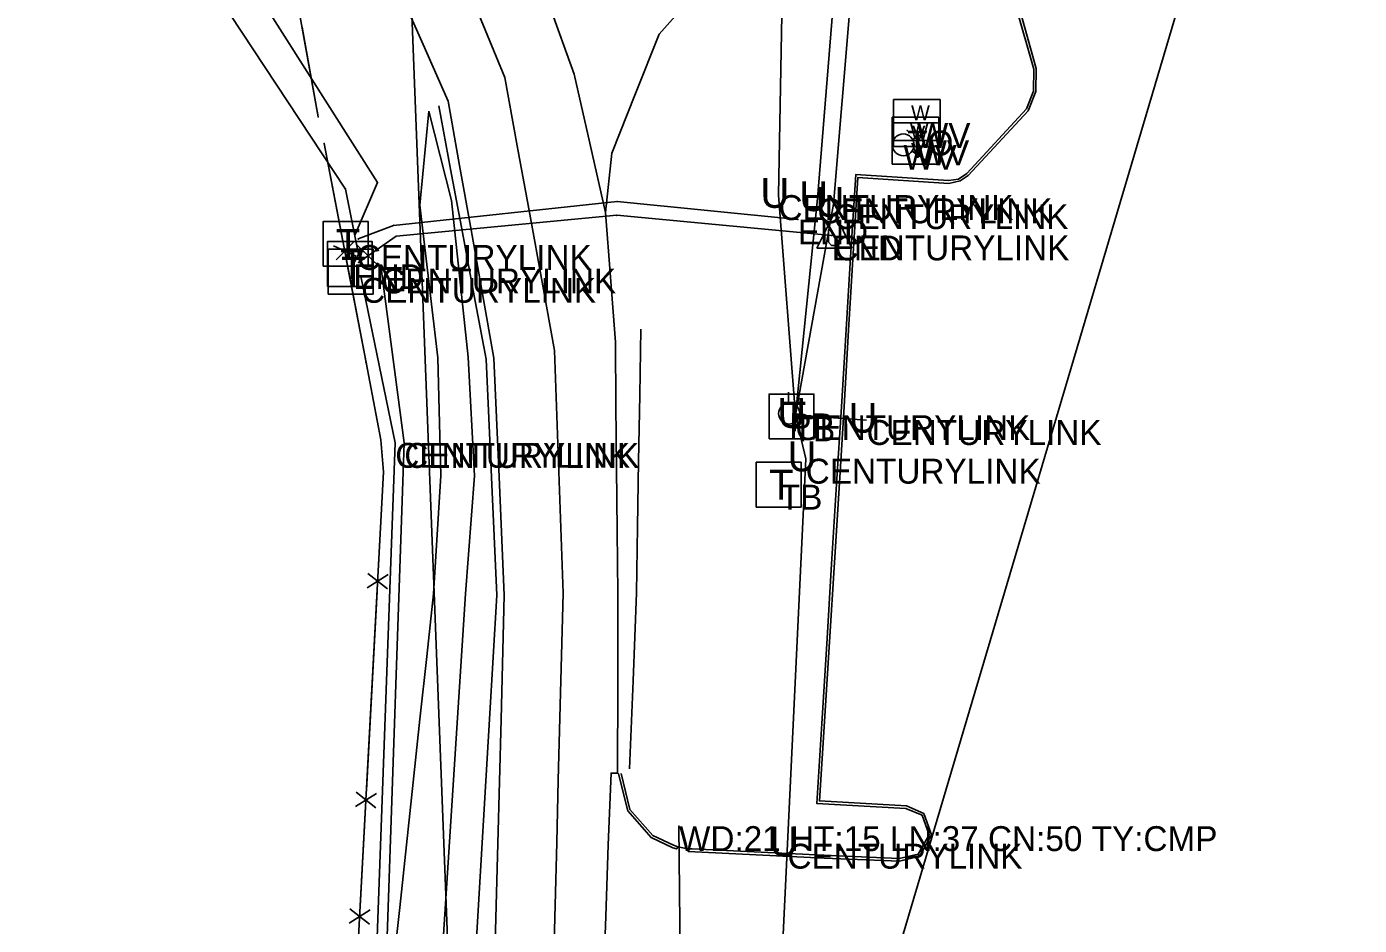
# Model space of a CAD drawing. Extents: x 675481 to 678499, y 212715 to 215285.
# Drawn here: x 677784.7 to 678052.3, y 214307.3 to 214487.7 of the extents above; entities that cross this region are included whole.
import ezdxf

# ---------------------------------------------------------------- set-up
doc = ezdxf.new("R2010")
doc.units = 0
for name, color, linetype in [('Default', 7, 'Continuous'), ('S_BASELINE', 7, 'Continuous'), ('S_CURB', 7, 'Continuous'), ('S_DITCHLINE', 7, 'Continuous'), ('S_DRG_PT_SYM', 7, 'Continuous'), ('S_EDGE_CONCRETE', 7, 'Continuous'), ('S_EDGE_PAVEMENT', 7, 'Continuous'), ('S_FENCE', 7, 'Continuous'), ('S_FIBER_OPTIC_CABLE', 7, 'Continuous'), ('S_FIBER_OPTIC_CABLE_ANNOT', 7, 'Continuous'), ('S_GAS_UTILITIES', 7, 'Continuous'), ('S_GRD_PT_SYM', 7, 'Continuous'), ('S_MISC_TOPO_POINT', 7, 'Continuous'), ('S_MSC_PT_SYM', 7, 'Continuous'), ('S_PAVEMENT_CROWN', 7, 'Continuous'), ('S_SHOULDER', 7, 'Continuous'), ('S_SIDE_DRAIN', 7, 'Continuous'), ('S_SIDE_DRAIN_ANNOT', 7, 'Continuous'), ('S_TELEPHONE_UTILITIES', 7, 'Continuous'), ('S_TELEPHONE_UTILITIES_ANNOT', 7, 'Continuous'), ('S_UNDERGROUND_CABLE', 7, 'Continuous'), ('S_UNDERGROUND_CABLE_ANNOT', 7, 'Continuous'), ('S_UTILITY_POLE', 7, 'Continuous'), ('S_UTILITY_POLE_ANNOT', 7, 'Continuous'), ('S_UTL_PT_SYM', 7, 'Continuous'), ('S_WATER_UTILITIES', 7, 'Continuous'), ('S_WATER_UTILITIES_ANNOT', 7, 'Continuous')]:
    doc.layers.add(name, color=color, linetype=linetype)

msp = doc.modelspace()

# ---------------------------------------------------------------- linework, layer by layer
at = {"layer": 'S_BASELINE'}
msp.add_line((677859.18, 214564.08), (677899.68, 213513.2), dxfattribs=at)
at = {"layer": 'S_CURB'}
for points in [[(677983.38, 214491.58), (677986.88, 214479.15), (677986.83, 214474.8), (677985.44, 214471.22), (677973.47, 214458.27), (677971.75, 214457.13), (677969.79, 214456.81), (677951.14, 214458.03), (677950.18, 214442.49), (677949.21, 214426.95), (677948.25, 214411.4), (677947.29, 214395.86), (677946.3, 214379.85), (677945.31, 214363.84), (677944.31, 214347.82), (677943.32, 214331.81), (677961.2, 214330.78), (677964.45, 214329.43), (677965.91, 214325.49), (677963.71, 214321.61), (677959.85, 214320.78), (677943.18, 214321.46), (677918.32, 214322.67), (677917.5, 214322.66)], [(677915.42, 214323.11), (677914.54, 214323.4), (677910.41, 214325.37), (677905.8, 214330.6), (677904.04, 214337.81)]]:
    msp.add_lwpolyline(points, dxfattribs=at)
at = {"layer": 'S_DITCHLINE'}
for points in [[(677865.39, 214470.74), (677863.64, 214451.91), (677865.44, 214436.57), (677867.24, 214421.23), (677867.8, 214397.65), (677866.34, 214373.89), (677864.99, 214361.29), (677863.63, 214348.69), (677862.28, 214336.09), (677860.92, 214323.49), (677859.57, 214310.89), (677858.21, 214298.29)], [(677865.39, 214470.73), (677869.96, 214452.85), (677871.64, 214437.1), (677873.32, 214421.35), (677874.57, 214397.53), (677872.78, 214373.88), (677871.17, 214348.99), (677869.56, 214324.09), (677867.96, 214299.2)]]:
    msp.add_lwpolyline(points, dxfattribs=at)
at = {"layer": 'S_DRG_PT_SYM'}
msp.add_lwpolyline([(677915.65, 214327.24), (677915.65, 214327.29), (677915.65, 214327.24), (677915.6, 214327.24), (677915.65, 214327.24), (677915.65, 214327.19), (677915.65, 214327.24), (677915.7, 214327.24)], dxfattribs=at)
at = {"layer": 'S_EDGE_CONCRETE'}
for points in [[(677983.94, 214491.55), (677987.36, 214479.34), (677987.34, 214474.7), (677985.8, 214470.8), (677973.74, 214457.87), (677972.1, 214456.76), (677969.82, 214456.26), (677951.58, 214457.47), (677950.65, 214442.13), (677949.72, 214426.8), (677948.79, 214411.47), (677947.86, 214396.13), (677946.86, 214380.17), (677945.86, 214364.22), (677944.85, 214348.26), (677943.85, 214332.3), (677961.35, 214331.29), (677964.81, 214329.76), (677966.35, 214325.51), (677964.01, 214321.19), (677959.9, 214320.23), (677944.79, 214320.79), (677931.14, 214321.48), (677917.49, 214322.16), (677917.37, 214322.7), (677915.49, 214323.09), (677915.18, 214322.67), (677914.38, 214322.92), (677910.03, 214324.97), (677905.39, 214330.3), (677903.51, 214337.76)], [(677903.51, 214337.76), (677903.32, 214337.87)]]:
    msp.add_lwpolyline(points, dxfattribs=at)
at = {"layer": 'S_EDGE_PAVEMENT'}
for points in [[(677836.94, 214575.26), (677848.31, 214564.09), (677859.68, 214552.92), (677870.73, 214537.2), (677877.66, 214521.64), (677884.59, 214506.09), (677889.61, 214492.12), (677894.63, 214478.16), (677897.75, 214464.3), (677900.87, 214450.43), (677901.87, 214437.41), (677902.87, 214424.38), (677903, 214411.76), (677903.13, 214399.15), (677903.26, 214386.53), (677903.39, 214373.91), (677903.35, 214355.89), (677903.32, 214337.87), (677902, 214337.89), (677901.46, 214323.49), (677900.93, 214309.09), (677900.4, 214294.69)], [(677820.84, 214556.56), (677834.52, 214538.62), (677848.19, 214520.68), (677853.46, 214508.7), (677858.73, 214496.72), (677864, 214484.74), (677869.27, 214472.76), (677871.58, 214459.86), (677873.89, 214446.96), (677876.2, 214434.06), (677878.5, 214421.16), (677879.53, 214397.37), (677880.55, 214373.58), (677879.91, 214348.66), (677879.26, 214323.75), (677878.61, 214298.83)], [(677902.14, 214462.33), (677906.9, 214474.28), (677911.66, 214486.23), (677926.85, 214503.34), (677936.11, 214511.45), (677948.81, 214516.49), (677961.5, 214521.54), (677974.19, 214526.58), (677986.88, 214531.62), (677998.97, 214534.94), (678011.07, 214538.25), (678023.16, 214541.57), (678035.25, 214544.88), (678054.98, 214548.6)], [(677900.87, 214450.43), (677902.14, 214462.33)]]:
    msp.add_lwpolyline(points, dxfattribs=at)
at = {"layer": 'S_FENCE'}
for p, q in [((677835.73, 214511.24), (677843.18, 214469.62)), ((677844.39, 214464.27), (677852.81, 214420.33)), ((677846.25, 214443.71), (677850.81, 214441.66)), ((677850.27, 214444.48), (677846.79, 214440.89)), ((677852.81, 214420.33), (677855.78, 214404.81)), ((677855.78, 214404.81), (677856.31, 214398.38)), ((677856.31, 214398.38), (677827.7, 213863.61)), ((677857.26, 214377.74), (677853.01, 214375.09)), ((677853.17, 214377.96), (677857.1, 214374.87)), ((677850.82, 214334.04), (677854.75, 214330.95)), ((677854.91, 214333.82), (677850.66, 214331.17)), ((677853.66, 214310.43), (677849.41, 214307.78)), ((677849.57, 214310.65), (677853.5, 214307.56))]:
    msp.add_line(p, q, dxfattribs=at)
for points in [[(677839.96, 214487.61), (677843.18, 214469.62)], [(677839.96, 214487.61), (677843.18, 214469.62)], [(677839.96, 214487.61), (677843.18, 214469.62)], [(677844.39, 214464.27), (677848.15, 214444.65)], [(677848.9, 214440.72), (677852.81, 214420.33)], [(677852.81, 214420.33), (677855.78, 214404.81)], [(677855.78, 214404.81), (677856.31, 214398.38)], [(677856.31, 214398.38), (677855.24, 214378.41)], [(677855.03, 214374.42), (677852.89, 214334.49)], [(677852.71, 214331.06), (677851.64, 214311.1)]]:
    msp.add_lwpolyline(points, dxfattribs=at)
at = {"layer": 'S_FIBER_OPTIC_CABLE'}
for p, q in [((677770.28, 214573.85), (677848.71, 214455.13)), ((677780.88, 214573.35), (677855.11, 214456.45)), ((677848.71, 214455.13), (677851.28, 214442.06)), ((677855.11, 214456.45), (677850.59, 214446.01)), ((677858.32, 214447.83), (677903.22, 214452.63)), ((677903.22, 214452.63), (677939.51, 214449)), ((677858.85, 214445.65), (677903.14, 214449.86)), ((677903.14, 214449.86), (677946.31, 214445.79)), ((677851.25, 214445.1), (677858.32, 214447.83)), ((677850.59, 214446.01), (677850.58, 214446.02)), ((677850.95, 214443.89), (677855.86, 214439.17)), ((677851.32, 214440.41), (677858.85, 214445.65)), ((677851.28, 214442.06), (677850.26, 214440.04)), ((677855.86, 214439.17), (677860.49, 214404.15)), ((677851.83, 214437.29), (677858.68, 214404.17)), ((677858.68, 214404.17), (677853.43, 214262.21)), ((677860.49, 214404.15), (677855.5, 214261.83))]:
    msp.add_line(p, q, dxfattribs=at)
at = {"layer": 'S_GAS_UTILITIES'}
msp.add_line((677939.09, 214232.8), (678023.84, 214518.55), dxfattribs=at)
at = {"layer": 'S_GRD_PT_SYM'}
for points in [[(677961.47, 214466.85), (677961.47, 214466.9), (677961.47, 214466.85), (677961.42, 214466.85), (677961.47, 214466.85), (677961.47, 214466.8), (677961.47, 214466.85), (677961.52, 214466.85)], [(677902.14, 214337.88), (677902.14, 214337.93), (677902.14, 214337.88), (677902.09, 214337.88), (677902.14, 214337.88), (677902.14, 214337.83), (677902.14, 214337.88), (677902.19, 214337.88)]]:
    msp.add_lwpolyline(points, dxfattribs=at)
at = {"layer": 'S_MSC_PT_SYM'}
for points in [[(677843.18, 214469.62), (677843.18, 214469.67), (677843.18, 214469.62), (677843.13, 214469.62), (677843.18, 214469.62), (677843.18, 214469.57), (677843.18, 214469.62), (677843.23, 214469.62)], [(677844.39, 214464.27), (677844.39, 214464.32), (677844.39, 214464.27), (677844.34, 214464.27), (677844.39, 214464.27), (677844.39, 214464.22), (677844.39, 214464.27), (677844.44, 214464.27)], [(677852.81, 214420.33), (677852.81, 214420.38), (677852.81, 214420.33), (677852.76, 214420.33), (677852.81, 214420.33), (677852.81, 214420.28), (677852.81, 214420.33), (677852.86, 214420.33)], [(677855.78, 214404.81), (677855.78, 214404.86), (677855.78, 214404.81), (677855.73, 214404.81), (677855.78, 214404.81), (677855.78, 214404.76), (677855.78, 214404.81), (677855.83, 214404.81)], [(677856.31, 214398.38), (677856.31, 214398.43), (677856.31, 214398.38), (677856.26, 214398.38), (677856.31, 214398.38), (677856.31, 214398.33), (677856.31, 214398.38), (677856.36, 214398.38)]]:
    msp.add_lwpolyline(points, dxfattribs=at)
at = {"layer": 'S_PAVEMENT_CROWN'}
msp.add_lwpolyline([(677830.11, 214566.89), (677845, 214547.51), (677859.89, 214528.12), (677865.08, 214515.47), (677870.27, 214502.82), (677875.46, 214490.17), (677880.66, 214477.51), (677883.16, 214463.81), (677885.67, 214450.11), (677888.18, 214436.41), (677890.68, 214422.71), (677891.52, 214398.36), (677892.37, 214374.01), (677892.05, 214361.49), (677891.73, 214348.97), (677891.41, 214336.45), (677891.1, 214323.93), (677890.78, 214311.4), (677890.46, 214298.88)], dxfattribs=at)
at = {"layer": 'S_SHOULDER'}
for points in [[(677867.4, 214471.84), (677869.79, 214459.13), (677872.17, 214446.42), (677874.55, 214433.71), (677876.94, 214421), (677878.02, 214397.3), (677879.09, 214373.6), (677877.62, 214348.74), (677876.14, 214323.88), (677874.67, 214299.02)], [(677907.97, 214426.99), (677907.76, 214413.76), (677907.55, 214400.52), (677907.34, 214387.29), (677907.13, 214374.06), (677906.43, 214356.41), (677905.73, 214338.76)]]:
    msp.add_lwpolyline(points, dxfattribs=at)
at = {"layer": 'S_SIDE_DRAIN'}
msp.add_line((677915.65, 214327.24), (677915.98, 214290.76), dxfattribs=at)
at = {"layer": 'S_TELEPHONE_UTILITIES'}
for points in [[(677844.2, 214439.62), (677844.2, 214448.62), (677853.2, 214448.62), (677853.2, 214439.62)], [(677845.06, 214435.56), (677845.06, 214444.56), (677854.06, 214444.56), (677854.06, 214435.56)], [(677845.23, 214434.04), (677845.23, 214443.04), (677854.23, 214443.04), (677854.23, 214434.04)], [(677933.75, 214404.96), (677933.75, 214413.96), (677942.75, 214413.96), (677942.75, 214404.96)], [(677931.17, 214391.27), (677931.17, 214400.27), (677940.17, 214400.27), (677940.17, 214391.27)]]:
    msp.add_lwpolyline(points, close=True, dxfattribs=at)
at = {"layer": 'S_UNDERGROUND_CABLE'}
for p, q in [((677935.63, 214453.9), (677936.41, 214495.85)), ((677943.45, 214453.24), (677946.88, 214495.38)), ((677946.68, 214452.08), (677950.17, 214493.98)), ((677939.03, 214409.72), (677935.63, 214453.9)), ((677939.03, 214409.72), (677943.45, 214453.24)), ((677939.03, 214409.72), (677946.68, 214452.08)), ((677946.87, 214450.33), (677943.34, 214443.24)), ((677946.87, 214450.33), (677950.36, 214443.24)), ((677945.67, 214444.48), (677945.67, 214446.92)), ((677948.03, 214446.92), (677948.03, 214444.48)), ((677946.29, 214443.82), (677945.67, 214444.48)), ((677947.49, 214443.82), (677946.29, 214443.82)), ((677948.03, 214444.48), (677947.49, 214443.82)), ((677943.34, 214443.24), (677950.36, 214443.24)), ((677939.03, 214409.72), (677941.1, 214400.99)), ((677939.03, 214409.72), (677953.32, 214408.75)), ((677941.1, 214400.99), (677937.44, 214323.71)), ((677937.44, 214323.71), (677933.51, 214243.69))]:
    msp.add_line(p, q, dxfattribs=at)
at = {"layer": 'S_UTILITY_POLE'}
msp.add_line((677937.66, 214412.21), (677937.66, 214414.32), dxfattribs=at)
msp.add_circle((677937.78, 214410.07), 2.13, dxfattribs=at)
at = {"layer": 'S_UTL_PT_SYM'}
for points in [[(677848.71, 214455.13), (677848.71, 214455.18), (677848.71, 214455.13), (677848.66, 214455.13), (677848.71, 214455.13), (677848.71, 214455.08), (677848.71, 214455.13), (677848.76, 214455.13)], [(677855.11, 214456.45), (677855.11, 214456.5), (677855.11, 214456.45), (677855.06, 214456.45), (677855.11, 214456.45), (677855.11, 214456.4), (677855.11, 214456.45), (677855.16, 214456.45)], [(677903.22, 214452.63), (677903.22, 214452.68), (677903.22, 214452.63), (677903.17, 214452.63), (677903.22, 214452.63), (677903.22, 214452.58), (677903.22, 214452.63), (677903.27, 214452.63)], [(677903.14, 214449.86), (677903.14, 214449.91), (677903.14, 214449.86), (677903.09, 214449.86), (677903.14, 214449.86), (677903.14, 214449.81), (677903.14, 214449.86), (677903.19, 214449.86)], [(677939.51, 214449), (677939.51, 214449.05), (677939.51, 214449), (677939.46, 214449), (677939.51, 214449), (677939.51, 214448.95), (677939.51, 214449), (677939.56, 214449)], [(677858.32, 214447.83), (677858.32, 214447.88), (677858.32, 214447.83), (677858.27, 214447.83), (677858.32, 214447.83), (677858.32, 214447.79), (677858.32, 214447.83), (677858.37, 214447.83)], [(677850.58, 214446.02), (677850.58, 214446.07), (677850.58, 214446.02), (677850.53, 214446.02), (677850.58, 214446.02), (677850.58, 214445.97), (677850.58, 214446.02), (677850.63, 214446.02)], [(677850.59, 214446.01), (677850.59, 214446.06), (677850.59, 214446.01), (677850.54, 214446.01), (677850.59, 214446.01), (677850.59, 214445.96), (677850.59, 214446.01), (677850.64, 214446.01)], [(677850.95, 214443.89), (677850.95, 214443.94), (677850.95, 214443.89), (677850.9, 214443.89), (677850.95, 214443.89), (677850.95, 214443.84), (677850.95, 214443.89), (677851, 214443.89)], [(677851.25, 214445.1), (677851.25, 214445.15), (677851.25, 214445.1), (677851.2, 214445.1), (677851.25, 214445.1), (677851.25, 214445.05), (677851.25, 214445.1), (677851.3, 214445.1)], [(677858.85, 214445.65), (677858.85, 214445.7), (677858.85, 214445.65), (677858.8, 214445.65), (677858.85, 214445.65), (677858.85, 214445.6), (677858.85, 214445.65), (677858.9, 214445.65)], [(677946.31, 214445.79), (677946.31, 214445.84), (677946.31, 214445.79), (677946.26, 214445.79), (677946.31, 214445.79), (677946.31, 214445.74), (677946.31, 214445.79), (677946.36, 214445.79)], [(677851.28, 214442.06), (677851.28, 214442.11), (677851.28, 214442.06), (677851.22, 214442.06), (677851.28, 214442.06), (677851.28, 214442.01), (677851.28, 214442.06), (677851.33, 214442.06)], [(677850.26, 214440.04), (677850.26, 214440.09), (677850.26, 214440.04), (677850.21, 214440.04), (677850.26, 214440.04), (677850.26, 214439.99), (677850.26, 214440.04), (677850.31, 214440.04)], [(677851.32, 214440.41), (677851.32, 214440.46), (677851.32, 214440.41), (677851.26, 214440.41), (677851.32, 214440.41), (677851.32, 214440.36), (677851.32, 214440.41), (677851.36, 214440.41)], [(677855.86, 214439.17), (677855.86, 214439.21), (677855.86, 214439.17), (677855.81, 214439.17), (677855.86, 214439.17), (677855.86, 214439.12), (677855.86, 214439.17), (677855.91, 214439.17)], [(677851.83, 214437.29), (677851.83, 214437.34), (677851.83, 214437.29), (677851.78, 214437.29), (677851.83, 214437.29), (677851.83, 214437.24), (677851.83, 214437.29), (677851.88, 214437.29)], [(677858.68, 214404.17), (677858.68, 214404.22), (677858.68, 214404.17), (677858.62, 214404.17), (677858.68, 214404.17), (677858.68, 214404.12), (677858.68, 214404.17), (677858.73, 214404.17)], [(677860.49, 214404.15), (677860.49, 214404.19), (677860.49, 214404.15), (677860.45, 214404.15), (677860.49, 214404.15), (677860.49, 214404.1), (677860.49, 214404.15), (677860.55, 214404.15)]]:
    msp.add_lwpolyline(points, dxfattribs=at)
at = {"layer": 'S_WATER_UTILITIES'}
for p, q in [((677958.7, 214473.07), (677968.11, 214473.07)), ((677958.7, 214463.66), (677958.7, 214473.07)), ((677968.11, 214473.07), (677968.11, 214463.66)), ((677958.44, 214469.56), (677967.86, 214469.56)), ((677958.44, 214460.14), (677958.44, 214469.56)), ((677958.7, 214468.38), (677968.11, 214468.38)), ((677967.86, 214469.56), (677967.86, 214460.14)), ((677962.59, 214465.04), (677965.41, 214466.77)), ((677958.44, 214464.87), (677967.86, 214464.87)), ((677968.11, 214463.66), (677958.7, 214463.66)), ((677962.47, 214462.73), (677965.37, 214460.81)), ((677967.86, 214460.14), (677958.44, 214460.14))]:
    msp.add_line(p, q, dxfattribs=at)
msp.add_circle((677960.69, 214463.99), 2.18, dxfattribs=at)

# ---------------------------------------------------------------- texts
at = {"layer": 'Default'}
for p in [(677932, 214451.35), (677939.82, 214450.69), (677943.05, 214449.53), (677935.4, 214407.18), (677935.4, 214407.18), (677935.4, 214407.18), (677935.4, 214407.18), (677935.4, 214407.18), (677949.69, 214406.21), (677937.47, 214398.45), (677933.81, 214321.16)]:
    msp.add_text('U', height=6, rotation=360, dxfattribs=at).set_placement(p)
at = {"layer": 'S_FIBER_OPTIC_CABLE_ANNOT'}
for s, p in [('END', (677939.51, 214444)), ('CENTURYLINK', (677850.95, 214438.89)), ('END', (677946.31, 214440.79)), ('END', (677850.26, 214435.04)), ('CENTURYLINK', (677855.86, 214434.17)), ('CENTURYLINK', (677851.83, 214432.29)), ('CENTURYLINK', (677858.68, 214399.17)), ('CENTURYLINK', (677860.49, 214399.15))]:
    msp.add_text(s, height=5, dxfattribs=at).set_placement(p)
at = {"layer": 'S_MISC_TOPO_POINT'}
msp.add_text('TO', height=5, dxfattribs=at).set_placement((677961.47, 214461.85))
at = {"layer": 'S_SIDE_DRAIN_ANNOT'}
msp.add_text('WD:21 HT:15 LN:37 CN:50 TY:CMP', height=5, dxfattribs=at).set_placement((677915.65, 214322.24))
at = {"layer": 'S_TELEPHONE_UTILITIES'}
for p in [(677846.76, 214441.12), (677847.62, 214437.06), (677847.79, 214435.54), (677936.31, 214406.46), (677933.74, 214392.77)]:
    msp.add_text('T', height=6, rotation=360, dxfattribs=at).set_placement(p)
at = {"layer": 'S_TELEPHONE_UTILITIES_ANNOT'}
for p in [(677938.48, 214404.48), (677935.9, 214390.78)]:
    msp.add_text('TB', height=5, dxfattribs=at).set_placement(p)
at = {"layer": 'S_UNDERGROUND_CABLE_ANNOT'}
for p in [(677935.63, 214448.9), (677943.45, 214448.24), (677946.68, 214447.08), (677939.03, 214404.72), (677939.03, 214404.72), (677939.03, 214404.72), (677939.03, 214404.72), (677939.03, 214404.72), (677953.32, 214403.75), (677941.1, 214395.99), (677937.44, 214318.71)]:
    msp.add_text('CENTURYLINK', height=5, dxfattribs=at).set_placement(p)
at = {"layer": 'S_UTILITY_POLE_ANNOT'}
for s, p in [('CENTURYLINK', (677946.87, 214440.8)), ('PP', (677937.78, 214405.07))]:
    msp.add_text(s, height=5, dxfattribs=at).set_placement(p)
at = {"layer": 'S_WATER_UTILITIES'}
for s, p in [('W', (677962.25, 214468.92)), ('W', (677961.99, 214465.4)), ('V', (677962.48, 214464.85)), ('V', (677962.23, 214461.34))]:
    msp.add_text(s, height=3, rotation=360, dxfattribs=at).set_placement(p)
at = {"layer": 'S_WATER_UTILITIES_ANNOT'}
for p in [(677963.41, 214463.39), (677960.69, 214458.99), (677963.15, 214459.87)]:
    msp.add_text('WV', height=5, dxfattribs=at).set_placement(p)

doc.saveas('drawing.dxf')
